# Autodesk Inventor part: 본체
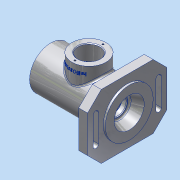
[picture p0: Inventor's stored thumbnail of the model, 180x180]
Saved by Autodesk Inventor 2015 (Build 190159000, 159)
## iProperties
Created: 2017-10
Part Number: 본체
Material: 알루미늄 6061
Document SubType Name: Modeling
Designer: Administrator
Density: 2.7 g/cm^3
Appearance: 알루미늄 - 평지
Mass: 781.743 g
Surface Area: 663.75 cm^2
Volume: 289.534 cm^3
Author: Administrator
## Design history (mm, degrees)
sketch "스케치1"
  geometry: C1 r 31 at (0, 0); 1 further point
  constraints: 1 centre point, 1 coincident
  dimensions: "d1" = 62 diameter of C1
extrude "돌출1" new body sketch "스케치1" stored distance "d2" = 99; taper "d3" = 0 deg
sketch "스케치2"
  geometry: L1 (-58, 47)-(58, 47); L2 (58, 47)-(58, -47); L3 (58, -47)-(-58, -47); L4 (-58, -47)-(-58, 47); 3 further points
  constraints: 8 end point, 2 midpoint, 2 parallel, 1 horizontal, 1 horizontal alignment, 1 perpendicular, 1 vertical alignment
  dimensions: "d4" = 116 distance between parallel lines of L2 L4; "d5" = 94 distance between parallel lines of L3 L1
extrude "돌출2" join sketch "스케치2" distance "d6" = 13; taper "d7" = 0 deg
chamfer "모따기1" distance "d8" = 20; stored, may be unused: second distance "d9" = 2, angle "d10" = 45 deg
sketch "스케치3"
  geometry: L1 (-46, 20)-(-46, -20); L2 (-50, 20)-(-50, -20); L3 (-42, -20)-(-42, 20); L4 (46, 20)-(46, -20); L5 (42, 20)-(42, -20); L6 (50, -20)-(50, 20); A1 r 4 centre (-46, 20) between (-42, 20) and (-50, 20); A2 r 4 centre (-46, -20) between (-50, -20) and (-42, -20); A3 r 4 centre (46, 20) between (50, 20) and (42, 20); A4 r 4 centre (46, -20) between (42, -20) and (50, -20); 3 further points
  constraints: 16 end point, 8 point on circle, 8 tangent, 4 centre point, 3 parallel, 2 horizontal alignment, 2 midpoint, 1 vertical
  dimensions: "d11" = 40 distance of L1.end L1.start; "d12" = 4 radius of A1; "d13" = 46 horizontal distance of point (0, 0) L1.end; "d14" = 4 radius of A3; "d15" = 92 distance of L4.end L1.end; "d16" = 40 distance of L4.end L4.start
extrude "돌출3" cut sketch "스케치3" stored distance "d17" = 13; taper "d18" = 0 deg
sketch "스케치4"
  geometry: C1 r 35 at (0, 0); 1 further point
  constraints: 1 centre point, 1 coincident
  dimensions: "d19" = 70 diameter of C1
extrude "돌출4" join sketch "스케치4" distance "d20" = 3; taper "d21" = 0 deg
sketch "스케치5"
  geometry: L1 (31, 49.5)-(-31, 49.5) reference; L2 (0, 49.5)-(0, -65.634); L3 (0, 49.5)-(21, 49.5); L4 (21, 49.5)-(21, 40.5); L5 (21, 40.5)-(24, 40.5); L6 (24, 40.5)-(24, 37.5); L7 (24, 37.5)-(21, 37.5); L8 (21, 37.5)-(21, 30.458); L9 (21, 30.458)-(17.5, 30.458); L10 (17.5, 30.458)-(17.5, 27.208); L11 (17.5, 27.208)-(18.5, 27.208); L12 (18.5, 27.208)-(18.5, 25.458); L13 (18.5, 25.458)-(17.5, 25.458); L14 (17.5, 25.458)-(17.5, 14.458); L15 (17.5, 14.458)-(0, 14.458); 1 further point
  constraints: 28 end point, 7 perpendicular, 4 vertical, 2 horizontal, 2 point on line, 1 midpoint
  dimensions: "d22" = 42 diameter of L4 L2; "d23" = 9 distance of L3.end L4.end; "d24" = 3 distance of L5.end L6.end; "d25" = 48 diameter of L6 L2; "d26" = 42 diameter of L8 L2; "d27" = 35 diameter of L10 L2; "d28" = 3.25 distance of L9.end L10.end; "d29" = 37 diameter of L12 L2; "d30" = 1.75 distance of L11.end L12.end; "d31" = 35 diameter of L14 L2; "d32" = 19.04189 distance between parallel lines of L9 L3; "d33" = 11 distance of L13.end L14.end
revolve "회전1" sketch "스케치5" stored, may be unused: angle "d34" = 90 deg
sketch "스케치6"
  geometry: L1 (0, 14.458)-(0, -65.5); L2 (0, 14.458)-(26, 14.458); L3 (17.5, 14.458)-(-17.5, 14.458) reference; L4 (26, 14.458)-(26, -23.542); L5 (26, -23.542)-(18.5, -23.542); L6 (18.5, -23.542)-(18.5, -34.542); L7 (18.5, -34.542)-(16.5, -34.542); L8 (16.5, -34.542)-(16.5, -39.542); L9 (16.5, -39.542)-(10, -39.542); L10 (10, -39.542)-(10, -42.242); L11 (10, -42.242)-(12.5, -42.242); L12 (12.5, -42.242)-(12.5, -49.542); L13 (12.5, -49.542)-(16, -49.5); L14 (-31, -49.5)-(31, -49.5) reference; L15 (16, -49.5)-(22, -65.5); L16 (-35, -65.5)-(35, -65.5) reference; L17 (22, -65.5)-(0, -65.5); 1 further point
  constraints: 28 end point, 9 perpendicular, 3 point on line, 2 collinear, 1 midpoint, 1 vertical
  dimensions: "d35" = 52 diameter of L4 L1; "d36" = 38 distance of L2.end L4.end; "d37" = 37 diameter of L6 L1; "d38" = 11 distance of L5.end L6.end; "d39" = 33 diameter of L8 L1; "d40" = 5 distance of L7.end L8.end; "d41" = 20 diameter of L10 L1; "d42" = 2.7 distance of L9.end L10.end; "d43" = 25 diameter of L12 L1; "d44" = 7.3 distance of L11.end L12.end; "d45" = 32 diameter of L13.end L1; "d46" = 44 diameter of L15.end L1
revolve "회전2" sketch "스케치6" stored, may be unused: angle "d47" = 90 deg
sketch "스케치7"
  geometry: L1 (7, -99)-(69, -99) reference; C1 r 25 at (38, -43); 2 further points
  constraints: 1 centre point, 1 midpoint, 1 vertical alignment
  dimensions: "d48" = 56 distance from line of L1 C1.centre; "d49" = 50 diameter of C1
extrude "돌출5" join sketch "스케치7" stored distance "d50" = 3; taper "d51" = 0 deg
sketch "스케치8"
  geometry: C1 r 25 at (0, 0) reference; 1 further point
hole "구멍1" sketch "스케치8" at (0, 0) diameter "d52" = 32; stored, may be unused: countersink angle "d56" = 90 deg, drill point angle "d58" = 118 deg; dims "d53" = 6, "d54" = 4, "d55" = 2, "d57" = 8
sketch "스케치9"
  geometry: C1 r 16 at (0, 0) reference; A1 r 20.5 centre (0, 0) between (-20.5, 0) and (20.5, 0); 1 further point
  constraints: 2 horizontal alignment, 2 point on circle, 1 centre point, 1 coincident
  dimensions: "d59" = 41 diameter of A1
hole "구멍2" sketch "스케치9" at (-20.5, 0), (20.5, 0) diameter "d60" = 2.459; stored, may be unused: countersink angle "d64" = 90 deg, drill point angle "d66" = 118 deg; dims "d61" = 6, "d62" = 4, "d63" = 2, "d65" = 8
chamfer "모따기2" distance "d67" = 1; stored, may be unused: second distance "d68" = 2, angle "d69" = 45 deg
feature "스레드1" dims "d70" = 10, "d71" = 0
fillet "모깎기1" dims "d76" = 3
fillet "모깎기2" dims "d77" = 0.3
chamfer "모따기3" distance "d78" = 0.7; stored, may be unused: second distance "d79" = 2, angle "d80" = 60 deg
fillet "모깎기3" dims "d81" = 3
chamfer "모따기4" distance "d82" = 1; stored, may be unused: second distance "d83" = 2, angle "d84" = 60 deg
node "작업 평면1"
sketch "스케치10"
  geometry: L1 (31, 49.5)-(-31, 49.5) reference; L2 (47, 18.5)-(47, -31.5) reference; 2 further points
  constraints: 1 other
  dimensions: "d86" = 56 distance from line of L1 point (37, -6.5); "d87" = 10 distance from line of point (37, -6.5) L2
feature "엠보싱1" sketch "스케치10" dims "d11" = 40, "d12" = 4, "d13" = 46, "d14" = 4, "d15" = 92, "d16" = 40, "d88" = 0.5, "d89" = 0
node "솔리드1"
other parameters: "d85" = 58.75
